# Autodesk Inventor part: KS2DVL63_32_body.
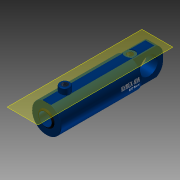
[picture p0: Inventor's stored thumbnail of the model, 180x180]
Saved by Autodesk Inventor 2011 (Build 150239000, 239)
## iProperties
Created: 2010-10
Document SubType Name: Modeling
Designer: TB
Mass: 405.061 g
Surface Area: 916.939 cm^2
Volume: 405.061 cm^3
Density: 1 g/cm^3
Author: TB
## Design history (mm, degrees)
sketch "Sketch2"
  geometry: L1 (-35, -3)-(-35, 3); L2 (-35, -9)-(-35, 9); L3 (-35, 0)-(-35, 36.5); L4 (-35, 36.5)-(-231, 36.5); L5 (-231, 36.5)-(-231, 36.5); L6 (-231, 36.5)-(-236, 36.5); L7 (-236, 36.5)-(-236, 20); L8 (-236, 20)-(-239, 17); L9 (-239, 17)-(-239, 16); L10 (-239, 16)-(-190, 16); L11 (-190, 16)-(-190, 31.5); L12 (-190, 31.5)-(-55, 31.5); L13 (-55, 31.5)-(-55, 0); L14 (-55, 0)-(-35, 0); L15 (-55, 0)-(-148.421, 0); L16 (-35, 9)-(-32, 12) reference; L17 (-32, 12)-(-35, 12) reference; L18 (-35, 12)-(-35, 9) reference; L19 (-32, 12)-(-35, 9) reference; L20 (-32, 12)-(-35, 12) reference; L21 (-35, 9)-(-35, 12) reference; L22 (-35, 9)-(-32, 12) reference; 1 further point
  constraints: 44 end point, 8 perpendicular, 6 parallel, 5 collinear, 2 horizontal, 2 vertical, 1 coincident, 1 midpoint, 1 point on line, 10 other
  dimensions: "DiaY" = 73 diameter of L4 L15; "DiaI" = 63 diameter of L12 L15; "d4" = 1 distance of L8.end L9.end; "d5" = 45 deg angle of L10 L8; "d6" = 3 distance between parallel lines of L7 L9; "DiaStang" = 32 diameter of L10 L15; "RindDia" = 73 diameter of L6 L15; "RingLengde" = 5 distance of L5.end L6.end; "RingTykk" = 46 distance between parallel lines of L11 L7; "KroppLengde" = 201 distance between parallel lines of L7 L3 (derived); "BunnTykkelse" = 20 distance between parallel lines of L13 L3
revolve "Kropp" sketch "Sketch2" stored, may be unused: angle "d13" = 90 deg
sketch "Sketch3"
  geometry: L1 (-55, -31.5)-(-55, 31.5) reference; L2 (-55, 0.01)-(-155, 0.01); L3 (-155, -0.01)-(-55, -0.01); A1 r 0.01 centre (-155, 0) between (-155, 0.01) and (-155, -0.01); A2 r 0.01 centre (-55, 0) between (-55, -0.01) and (-55, 0.01); 2 further points
  constraints: 4 end point, 4 point on circle, 4 tangent, 2 centre point, 1 coincident, 1 midpoint, 1 parallel, 1 perpendicular
  dimensions: "d17" = 0.01 radius of A2; "d18" = 100 distance of L2.start L2.end (= Slaglengde)
feature "BaneTransitionalConstraint" sketch "Sketch3" dims "d19" = 2, "d20" = 0
sketch "Sketch6"
  geometry: L1 (-51.1, 0)-(51.1, 0) reference; L2 (10.356, 35)-(-10.356, 35); L3 (36.5, 0)-(36.5, 31.248); L4 (-36.5, 0)-(-36.5, -18.451); A1 r 36.5 centre (0, 0) between (10.356, 35) and (-10.356, 35) reference; 1 further point
  constraints: 6 end point, 4 point on circle, 2 tangent
  dimensions: "d30" = 35 distance from line of A1.centre L2 (computed from DiaY); "d31" = 0 deg angle of L1 L2 (computed from Vinkel_Plussport); "d37" = 90 deg angle of L2 L3; "d38" = 90 deg angle of L2 L4
  node "Projected Loop3"
workplane "Work Plane5"
sketch "Sketch7"
  geometry: L1 (10.356, -286.8)-(10.356, 47.8) reference; L2 (-19.633, -35)-(38.367, -35) reference; C1 r 12.5 at (10.356, -52.5); 1 further point
  constraints: 1 centre point, 1 point on line
  dimensions: "PortDia" = 25 diameter of C1
extrude "Extrusion2" cut sketch "Sketch7" stored distance "d34" = 1.5; taper "d35" = 0 deg
workplane "Work Plane7"
sketch "Sketch4" dims "d144" = 10, "d145" = 0
  geometry: L1 (-16.68, -40)-(-16.68, -78.777); L2 (-16.68, -78.777)-(16.68, -78.777); L3 (16.68, -78.777)-(16.68, -40); L4 (16.68, -40)-(-16.68, -40); L5 (-40.643, -40)-(0, -40); L6 (-29, -35)-(29, -35) reference; L7 (0, -35)-(0, -40); 3 further points
  constraints: 4 end point, 2 midpoint, 1 perpendicular, 2 other
  dimensions: "d40" = 5 distance of L7.start L5.end
emboss "Emboss1" sketch "Sketch4" dims "d4" = 1, "d5" = 45 deg, "d6" = 3, "d22" = 0.2, "d23" = 0, "DiaI" = 63, "DiaY" = 73, "RindDia" = 73, "DiaStang" = 32, "RingTykk" = 46, "RingLengde" = 5, "KroppLengde" = 201 (derived), "BunnTykkelse" = 20
workplane "Work Plane8"
sketch "Sketch8"
  geometry: L1 (-29, -35)-(29, -35) reference; L2 (0, -35)-(0, -40); L3 (-5.906, -110.587)-(-5.906, -40); L4 (-5.906, -40)-(5.906, -40); L5 (5.906, -40)-(5.906, -110.587); L6 (5.906, -110.587)-(-5.906, -110.587); 3 further points
  constraints: 2 end point, 2 midpoint, 1 perpendicular, 2 other
  dimensions: "d42" = 5 distance of L2.start L2.end
emboss "Emboss2" sketch "Sketch8" dims "d4" = 1, "d5" = 45 deg, "d6" = 3, "d43" = 0.2, "d44" = 0, "DiaI" = 63, "DiaY" = 73, "RindDia" = 73, "DiaStang" = 32, "RingTykk" = 46, "RingLengde" = 5, "KroppLengde" = 201 (derived), "BunnTykkelse" = 20
sketch "Sketch9"
  geometry: A1 r 12.5 centre (9.367, -52.5) between (0, -60.776) and (18.735, -60.776) reference; 1 further point
hole "Hole1" sketch "Sketch9" at (9.367, -52.5) diameter "d45" = 14.95; stored, may be unused: countersink angle "d49" = 82 deg, drill point angle "d51" = 118 deg; dims "d46" = 6, "d47" = 3.023, "d48" = 2, "DiaInvPluss" = 15
workplane "Work Plane9"
sketch "Sketch10"
  geometry: L1 (-51.1, 0)-(51.1, 0) reference; L2 (0, 36.5)-(13.136, 36.5); L3 (0, 36.5)-(0, 31.79); L4 (12.5, 34.293)-(12.5, 50.5); L5 (12.5, 50.5)-(0, 50.5); L6 (0, 50.5)-(0, 36.5); L7 (0, 36.5)-(12.5, 34.293); C1 r 36.5 at (0, 0) reference; A1 r 36.5 centre (0, 0) between (0, 36.5) and (12.5, 34.293); 1 further point
  constraints: 12 end point, 4 perpendicular, 2 concentric, 2 point on circle, 1 centre point, 1 point on line, 1 tangent
  dimensions: "d53" = 0 deg angle of L1 L2 (computed from Vinkel_Minusport); "DiaUtvStussMinus" = 25 diameter of L4 L3; "HøydeStussMinuss" = 14 distance between parallel lines of L2 L5
revolve "Revolution2" sketch "Sketch10" stored, may be unused: angle "d56" = 90 deg
hole "Hole2" diameter "d59" = 14.95; stored, may be unused: countersink angle "d63" = 82 deg, drill point angle "d65" = 118 deg; dims "d57" = 10, "d58" = 10, "d60" = 6, "d61" = 3.023, "d62" = 2, "DiaInvStussMinus" = 14
fillet "Fillet1" dims "d66" = 2
sketch "Sketch15"
  geometry: L1 (14, -33.708)-(14, 33.708); L2 (-14, -33.708)-(-14, 33.708); L3 (0, 51.1)-(0, -51.1) reference; A1 r 36.5 centre (0, 0) between (14, -33.708) and (-14, -33.708) reference; A2 r 36.5 centre (0, 0) between (14, 33.708) and (-14, 33.708); A3 r 36.5 centre (0, 0) between (-14, -33.708) and (14, -33.708)
  constraints: 8 point on circle, 4 end point, 4 point on line, 2 centre point, 2 concentric, 2 parallel, 1 coincident
  dimensions: "EyeBunnTykk" = 14 distance from line of L1 A1.centre; "EyeBunnTykk2" = 14 distance from line of A1.centre L2
extrude "Extrusion6" join sketch "Sketch15" taper "d98" = 0 deg; distance "LengdeEyeMinussBunntykk" = 75
sketch "Sketch16"
  geometry: L1 (-235, 36.5)-(40, 36.5) reference; L2 (-235, -36.5)-(40, -36.5) reference; L3 (-235, 36.5)-(40, 36.5) reference; L4 (40, 36.5)-(40, 33.708) reference; L5 (40, -33.708)-(40, 33.708) reference; L6 (-291.181, 0)-(102.083, 0) reference; L7 (11.5, 36.5)-(40, 36.5); L8 (40, 36.5)-(40, 8); A1 r 28.5 centre (11.5, 8) between (40, 8) and (11.5, 36.5); 6 further points; 2 other entities
  constraints: 4 end point, 4 tangent, 2 point on circle, 2 point on line, 1 centre point, 1 collinear, 1 perpendicular, 2 other
  dimensions: "d137" = 8 distance from line of L8.end L6
extrude "Extrusion7" cut sketch "Sketch16" stored distance "d101" = 28; taper "d102" = 0 deg
mirror "Mirror1"
sketch "Sketch20"
  geometry: L1 (40, 36.5)-(40, 33.708) reference; L2 (-290, 0)-(95, 0) reference; L3 (21.344, 15.366)-(2.962, 25.979); L4 (2.962, 25.979)-(-4, 29.998); A1 r 12.207 centre (15.24, 4.794) between (27, 8.069) and (21.344, 15.366); A2 r 30 centre (-12.038, -0.002) between (2.962, 25.979) and (-12.038, 29.998); 4 further points; 2 other entities
  constraints: 4 end point, 4 point on circle, 2 centre point, 2 tangent, 1 collinear, 1 point on line, 6 other
  dimensions: "d139" = 8.06884 distance from line of A1.start L2; "d140" = 22.66455 dimension on point (17.335, 0); "d141" = 30 deg angle to the sketch x axis of L4; "d142" = 12.20713 radius of A1; "d143" = 30 radius of A2
extrude "Extrusion10" cut sketch "Sketch20" stored distance "d144" = 10; taper "d145" = 0 deg
mirror "Mirror2"
sketch "Sketch17"
  geometry: L1 (67.417, 0)-(0, 0) reference; L2 (33.708, -259.8)-(33.708, 130.8) reference; C1 r 20 at (33.708, 40); 1 further point
  constraints: 1 centre point, 1 point on line
  dimensions: "DiaHullEyeBunn" = 40 diameter of C1; "d125" = 40 distance from line of C1.centre L1
extrude "Extrusion8" cut sketch "Sketch17" distance "d104" = 28; taper "d105" = 0 deg
pattern_circular "Circular Pattern1 Only Subsea" dims "d108" = 180 deg (derived)
workplane "Work Plane11"
sketch "Sketch18"
  geometry: L1 (0, -58.8)-(0, 9.8) reference; L2 (31.5, -55)-(-31.5, -55) reference; C1 r 12.5 at (0, -28); 1 further point
  constraints: 1 centre point
  dimensions: "DiaForsenkPlussPort" = 25 diameter of C1; "PlassPlussport" = 27 distance from line of L2 C1.centre
extrude "Extrusion9" cut sketch "Sketch18" stored distance "d113" = 10; taper "d114" = 0 deg
sketch "Sketch19"
  geometry: 10 further points
  constraints: 1 other
hole "Hole3" sketch "Sketch19" at (0, -28) diameter "d115" = 14.95; stored, may be unused: countersink angle "d119" = 90 deg, drill point angle "d121" = 118 deg; dims "d116" = 6, "d117" = 4, "d118" = 2, "d120" = 14.5
pattern_circular "Circular Pattern2 Only Subsea" dims angle "d123" = 360 deg
body "Solid1"
chamfer "Chamfer" distance "Chamfer" = 1; stored, may be unused: second distance "d15" = 2, angle "d16" = 45 deg
node "Projected Loop2"
body "Srf1"
node "Projected Loop4"
node "Projected Loop5"
node "Projected Loop10"
other parameters: "Slaglengde" = 100, "Forlengelse_rør" = 0, "Vinkel_Plussport" = 0 [user parameter; used in 1 equation term], "Vinkel_Minusport" = 0, "d32" = 90 deg, "d39" = 90 deg, "d41" = 90 deg, "PortMinusPlass" = -46, "Minusport2" = 180 deg, "ForsenkningPlussPort" = 34.7 (derived)
